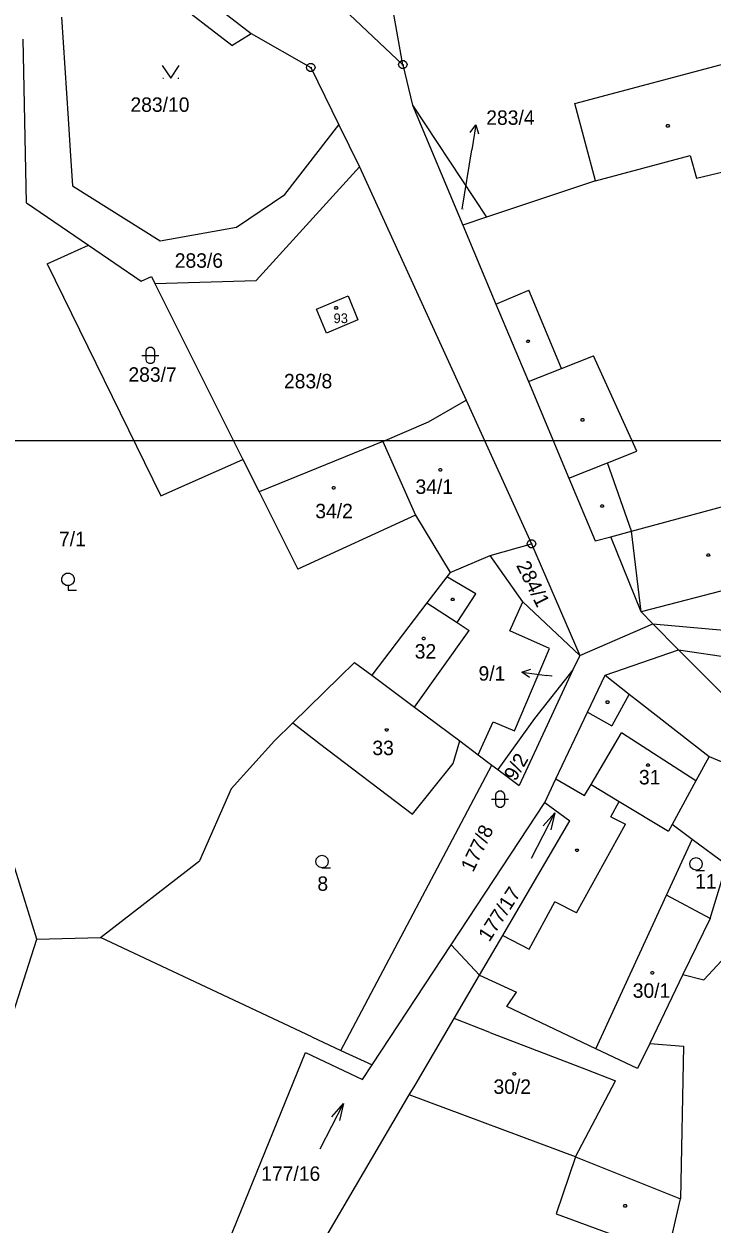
# Model space of a CAD drawing. Extents: x -780000 to -777378, y -1011169 to -1009297.
# Drawn here: x -779250.3 to -779169.3, y -1010360.1 to -1010218.8 of the extents above; entities that cross this region are included whole.
import ezdxf

# ---------------------------------------------------------------- set-up
doc = ezdxf.new("R2010")
doc.units = 0
for name, color, linetype in [('Default', 7, 'Continuous'), ('KN_HRANICE', 7, 'Continuous'), ('KN_KULTURY', 7, 'Continuous'), ('KN_PARCELY', 7, 'Continuous'), ('KN_SLUCKY', 7, 'Continuous'), ('LEGENDA', 7, 'Continuous')]:
    doc.layers.add(name, color=color, linetype=linetype)

# ---------------------------------------------------------------- blocks, each defined once
blk = doc.blocks.new('304')
at = {"layer": 'Default'}
blk.add_lwpolyline([(0, 0), (-0.38, 0.1), (-0.65, 0.37), (-0.75, 0.74), (-0.65, 1.11), (-0.38, 1.38), (-0.01, 1.48), (0.36, 1.38), (0.63, 1.11), (0.73, 0.73), (0.63, 0.35), (0.36, 0.08), (-0.02, -0.02), (0.98, -0.02)], dxfattribs=at)
blk = doc.blocks.new('305')
at = {"layer": 'Default'}
blk.add_lwpolyline([(0, 0.53), (-0.19, 0.53), (-0.53, 0.72), (-0.72, 1.06), (-0.72, 1.45), (-0.53, 1.79), (-0.19, 1.98), (0.2, 1.98), (0.54, 1.79), (0.73, 1.45), (0.73, 1.06), (0.54, 0.72), (0.2, 0.53), (0.01, 0.53), (0.01, 0), (1.01, 0)], dxfattribs=at)
blk = doc.blocks.new('314')
at = {"layer": 'Default'}
for p, q in [((-0.95, 0), (-0.85, 0)), ((0.85, 0), (0.95, 0))]:
    blk.add_line(p, q, dxfattribs=at)
blk.add_lwpolyline([(-1, 1.5), (0, 0), (1, 1.5)], dxfattribs=at)
blk = doc.blocks.new('316')
at = {"layer": 'Default'}
for points in [[(-0.5, 1.5), (-0.4, 1.79), (-0.15, 1.97), (0.16, 1.97), (0.41, 1.79), (0.51, 1.5), (0.51, 0.5), (0.41, 0.21), (0.16, 0.03), (-0.15, 0.03), (-0.4, 0.21), (-0.5, 0.5), (-0.5, 1.5)], [(-1, 1), (0.27, 1), (1, 1)]]:
    blk.add_lwpolyline(points, dxfattribs=at)
blk = doc.blocks.new('NAHRADNI_SYMBOL')
at = {"layer": 'Default'}
blk.add_lwpolyline([(0.09, 0.15), (0.18, 0), (0.09, -0.15), (-0.09, -0.15), (-0.18, 0), (-0.09, 0.15), (0.09, 0.15)], dxfattribs=at)
blk = doc.blocks.new('802')
at = {"layer": 'Default'}
blk.add_line((-3, 0), (3, 0), dxfattribs=at)
blk.add_lwpolyline([(1, 0.5), (3, 0), (1, -0.5)], dxfattribs=at)
blk = doc.blocks.new('10292')
at = {"layer": 'Default'}
blk.add_line((0, 3), (0, 0), dxfattribs=at)
blk.add_lwpolyline([(-0.5, 2), (0, 3), (0.5, 2)], dxfattribs=at)
blk = doc.blocks.new('402')
at = {"layer": 'Default'}
blk.add_lwpolyline([(0.09, 0.15), (0.18, 0), (0.09, -0.15), (-0.09, -0.15), (-0.18, 0), (-0.09, 0.15), (0.09, 0.15)], dxfattribs=at)
blk = doc.blocks.new('105')
at = {"layer": 'Default'}
blk.add_line((-0.12, 0), (0.12, 0), dxfattribs=at)
blk.add_lwpolyline([(0.15, 0.48), (0.4, 0.3), (0.5, 0.01), (0.4, -0.28), (0.15, -0.46), (-0.16, -0.46), (-0.41, -0.28), (-0.51, 0.01), (-0.41, 0.3), (-0.16, 0.48), (0.15, 0.48)], dxfattribs=at)

msp = doc.modelspace()

# ---------------------------------------------------------------- linework, layer by layer
at = {"layer": 'KN_HRANICE'}
for p, q in [((-779205.69, -1010223.63), (-779207.96, -1010210.85)), ((-779234.04, -1010211.86), (-779223.57, -1010219.94)), ((-779225.85, -1010221.36), (-779236.27, -1010213.3)), ((-779213.39, -1010216.37), (-779205.69, -1010223.63)), ((-779245.92, -1010218.02), (-779245.13, -1010229.97)), ((-779225.85, -1010221.36), (-779223.57, -1010219.94)), ((-779223.57, -1010219.94), (-779216.54, -1010223.96)), ((-779250.04, -1010239.9), (-779250.45, -1010220.64)), ((-779216.54, -1010223.96), (-779213.22, -1010230.72)), ((-779205.69, -1010223.63), (-779204.56, -1010228.41)), ((-779185.42, -1010228.21), (-779166.52, -1010223.19)), ((-779204.56, -1010228.41), (-779198.63, -1010242.53)), ((-779204.56, -1010228.41), (-779195.85, -1010241.6)), ((-779182.98, -1010237.3), (-779185.42, -1010228.21)), ((-779245.13, -1010229.97), (-779244.88, -1010233.78)), ((-779219.59, -1010238.93), (-779213.22, -1010230.72)), ((-779213.22, -1010230.72), (-779210.79, -1010235.65)), ((-779244.88, -1010233.78), (-779244.61, -1010237.88)), ((-779222.98, -1010249.03), (-779210.79, -1010235.65)), ((-779210.79, -1010235.65), (-779198.24, -1010263.13)), ((-779244.61, -1010237.88), (-779234.3, -1010244.39)), ((-779182.98, -1010237.3), (-779195.85, -1010241.6)), ((-779225.31, -1010242.76), (-779219.59, -1010238.93)), ((-779250.04, -1010239.9), (-779242.75, -1010244.88)), ((-779248.83, -1010326.61), (-779275.45, -1010241.64)), ((-779195.85, -1010241.6), (-779198.63, -1010242.53)), ((-779198.63, -1010242.53), (-779194.73, -1010251.82)), ((-779234.3, -1010244.39), (-779225.31, -1010242.76)), ((-779247.62, -1010247.08), (-779242.75, -1010244.88)), ((-779242.75, -1010244.88), (-779236.53, -1010249.13)), ((-779247.62, -1010247.08), (-779234.22, -1010274.39)), ((-779236.53, -1010249.13), (-779235.31, -1010248.59)), ((-779235.31, -1010248.59), (-779234.91, -1010249.39)), ((-779234.91, -1010249.39), (-779222.98, -1010249.03)), ((-779234.91, -1010249.39), (-779224.53, -1010270.12)), ((-779215.86, -1010252.41), (-779212.13, -1010250.84)), ((-779212.13, -1010250.84), (-779211.01, -1010253.67)), ((-779214.7, -1010255.23), (-779215.86, -1010252.41)), ((-779194.73, -1010251.82), (-779190.9, -1010260.95)), ((-779211.01, -1010253.67), (-779214.7, -1010255.23)), ((-779190.9, -1010260.95), (-779186.13, -1010272.3)), ((-779202.67, -1010265.7), (-779198.24, -1010263.13)), ((-779198.24, -1010263.13), (-779190.52, -1010280.05)), ((-779208.06, -1010267.99), (-779202.67, -1010265.7)), ((-779208.06, -1010267.99), (-779222.63, -1010273.91)), ((-779208.06, -1010267.99), (-779204.18, -1010276.69)), ((-779234.22, -1010274.39), (-779224.53, -1010270.12)), ((-779224.53, -1010270.12), (-779222.63, -1010273.91)), ((-779186.13, -1010272.3), (-779183.03, -1010279.71)), ((-779222.63, -1010273.91), (-779218.06, -1010283.04)), ((-779204.18, -1010276.69), (-779218.06, -1010283.04)), ((-779204.18, -1010276.69), (-779202.14, -1010280.06)), ((-779183.03, -1010279.71), (-779181.19, -1010279.22)), ((-779177.62, -1010288.07), (-779181.19, -1010279.22)), ((-779202.14, -1010280.06), (-779200.12, -1010283.41)), ((-779195.39, -1010281.41), (-779190.52, -1010280.05)), ((-779190.52, -1010280.05), (-779184.85, -1010293.19)), ((-779200.12, -1010283.41), (-779195.39, -1010281.41)), ((-779191.55, -1010286.87), (-779195.39, -1010281.41)), ((-779200.12, -1010283.41), (-779200.51, -1010283.92)), ((-779159.28, -1010283.29), (-779177.62, -1010288.07)), ((-779200.51, -1010283.92), (-779202.85, -1010286.98)), ((-779202.85, -1010286.98), (-779209.36, -1010295.51)), ((-779193.1, -1010290.28), (-779191.55, -1010286.87)), ((-779191.55, -1010286.87), (-779184.85, -1010293.19)), ((-779177.62, -1010288.07), (-779176.23, -1010289.47)), ((-779188.41, -1010292.39), (-779193.1, -1010290.28)), ((-779184.85, -1010293.19), (-779176.23, -1010289.47)), ((-779176.23, -1010289.47), (-779173.19, -1010292.52)), ((-779176.23, -1010289.47), (-779156.62, -1010291.23)), ((-779192.55, -1010302.07), (-779188.41, -1010292.39)), ((-779184.85, -1010293.19), (-779185.64, -1010294.9)), ((-779181.85, -1010295.53), (-779173.19, -1010292.52)), ((-779173.19, -1010292.52), (-779168.03, -1010297.71)), ((-779173.19, -1010292.52), (-779166.79, -1010293.46)), ((-779211.37, -1010294.01), (-779213.17, -1010295.76)), ((-779211.37, -1010294.01), (-779209.36, -1010295.51)), ((-779213.17, -1010295.76), (-779218.66, -1010301.14)), ((-779209.36, -1010295.51), (-779204.33, -1010299.27)), ((-779185.64, -1010294.9), (-779191.98, -1010308.5)), ((-779183.92, -1010299.88), (-779181.85, -1010295.53)), ((-779181.85, -1010295.53), (-779179.01, -1010297.75)), ((-779179.01, -1010297.75), (-779177.81, -1010298.69)), ((-779177.81, -1010298.69), (-779169.61, -1010305.1)), ((-779204.33, -1010299.27), (-779198.99, -1010303.26)), ((-779187.65, -1010307.74), (-779183.92, -1010299.88)), ((-779218.66, -1010301.14), (-779220.82, -1010303.25)), ((-779218.66, -1010301.14), (-779215.5, -1010303.55)), ((-779196.83, -1010304.88), (-779195.06, -1010301.02)), ((-779195.06, -1010301.02), (-779192.55, -1010302.07)), ((-779225.92, -1010308.91), (-779220.82, -1010303.25)), ((-779199.75, -1010305.93), (-779198.99, -1010303.26)), ((-779198.99, -1010303.26), (-779196.83, -1010304.88)), ((-779215.5, -1010303.55), (-779204.57, -1010311.9)), ((-779212.98, -1010339.7), (-779195.2, -1010306.1)), ((-779204.57, -1010311.9), (-779199.75, -1010305.93)), ((-779196.83, -1010304.88), (-779195.2, -1010306.1)), ((-779195.2, -1010306.1), (-779194.49, -1010306.63)), ((-779169.61, -1010305.1), (-779171.15, -1010307.94)), ((-779169.61, -1010305.1), (-779160.99, -1010308.63)), ((-779194.49, -1010306.63), (-779191.98, -1010308.5)), ((-779225.92, -1010308.91), (-779229.64, -1010317.38)), ((-779188.97, -1010310.51), (-779187.65, -1010307.74)), ((-779187.65, -1010307.74), (-779184.27, -1010309.7)), ((-779184.27, -1010309.7), (-779183.51, -1010308.4)), ((-779183.51, -1010308.4), (-779180.21, -1010310.38)), ((-779171.15, -1010307.94), (-779173.96, -1010313.1)), ((-779180.21, -1010310.38), (-779174.39, -1010313.89)), ((-779200, -1010327.27), (-779188.97, -1010310.51)), ((-779188.97, -1010310.51), (-779186, -1010312.66)), ((-779190.73, -1010320.73), (-779186, -1010312.66)), ((-779173.96, -1010313.1), (-779174.39, -1010313.89)), ((-779171.61, -1010314.85), (-779173.96, -1010313.1)), ((-779174.62, -1010321.41), (-779171.61, -1010314.85)), ((-779167.55, -1010317.87), (-779171.61, -1010314.85)), ((-779241.34, -1010326.4), (-779229.64, -1010317.38)), ((-779169.49, -1010324.18), (-779167.55, -1010317.87)), ((-779193.92, -1010326.17), (-779190.73, -1010320.73)), ((-779169.49, -1010324.18), (-779174.62, -1010321.41)), ((-779169.49, -1010324.18), (-779172.68, -1010330.78)), ((-779253.82, -1010342.15), (-779248.83, -1010326.61)), ((-779248.83, -1010326.61), (-779241.34, -1010326.4)), ((-779216.41, -1010338.1), (-779241.34, -1010326.4)), ((-779209.31, -1010341.42), (-779200, -1010327.27)), ((-779200, -1010327.27), (-779196.66, -1010330.84)), ((-779196.66, -1010330.84), (-779193.92, -1010326.17)), ((-779170.22, -1010331.41), (-779167.12, -1010328.04)), ((-779199.66, -1010335.95), (-779196.66, -1010330.84)), ((-779196.66, -1010330.84), (-779192.3, -1010332.84)), ((-779172.68, -1010330.78), (-779176.6, -1010338.9)), ((-779172.68, -1010330.78), (-779170.22, -1010331.41)), ((-779193.43, -1010334.55), (-779192.3, -1010332.84)), ((-779182.94, -1010339.51), (-779193.43, -1010334.55)), ((-779204.25, -1010343.79), (-779199.66, -1010335.95)), ((-779216.41, -1010338.1), (-779212.98, -1010339.7)), ((-779227.1, -1010364.33), (-779217.17, -1010339.95)), ((-779212.98, -1010339.7), (-779209.31, -1010341.42)), ((-779178.02, -1010341.84), (-779182.94, -1010339.51)), ((-779176.6, -1010338.9), (-779178.02, -1010341.84)), ((-779176.6, -1010338.9), (-779172.6, -1010339.21)), ((-779172.6, -1010339.21), (-779172.96, -1010357.18)), ((-779204.93, -1010344.94), (-779204.25, -1010343.79)), ((-779217.76, -1010366.81), (-779204.93, -1010344.94)), ((-779185.33, -1010352.25), (-779204.93, -1010344.94)), ((-779185.33, -1010352.25), (-779187.61, -1010358.93)), ((-779174.51, -1010363.75), (-779172.96, -1010357.18)), ((-779187.61, -1010358.93), (-779174.51, -1010363.75))]:
    msp.add_line(p, q, dxfattribs=at)
for points in [[(-779185.64, -1010294.9), (-779190.18, -1010300.61), (-779194.49, -1010306.63)], [(-779217.17, -1010339.95), (-779210.43, -1010343.11), (-779209.31, -1010341.42)]]:
    msp.add_lwpolyline(points, dxfattribs=at)
at = {"layer": 'KN_PARCELY'}
for p, q in [((-779198.7, -1010240.65), (-779197.58, -1010233.67)), ((-779188.12, -1010295.64), (-779188.71, -1010295.56))]:
    msp.add_line(p, q, dxfattribs=at)
at = {"layer": 'KN_SLUCKY'}
for p, q in [((-779182.98, -1010237.3), (-779171.83, -1010234.32)), ((-779171.83, -1010234.32), (-779171.09, -1010237.01)), ((-779171.09, -1010237.01), (-779166.12, -1010235.81)), ((-779194.73, -1010251.82), (-779190.86, -1010250.19)), ((-779186.99, -1010259.4), (-779190.86, -1010250.19)), ((-779186.99, -1010259.4), (-779183.21, -1010257.9)), ((-779178.12, -1010269.14), (-779183.21, -1010257.9)), ((-779190.9, -1010260.95), (-779186.99, -1010259.4)), ((-779181.59, -1010270.51), (-779178.12, -1010269.14)), ((-779186.13, -1010272.3), (-779181.59, -1010270.51)), ((-779178.75, -1010278.56), (-779181.59, -1010270.51)), ((-779178.75, -1010278.56), (-779161.78, -1010273.99)), ((-779181.19, -1010279.22), (-779178.75, -1010278.56)), ((-779177.62, -1010288.07), (-779178.75, -1010278.56)), ((-779197.09, -1010285.92), (-779200.51, -1010283.92)), ((-779199.3, -1010289.31), (-779197.09, -1010285.92)), ((-779202.85, -1010286.98), (-779199.3, -1010289.31)), ((-779204.33, -1010299.27), (-779197.88, -1010290.24)), ((-779199.3, -1010289.31), (-779197.88, -1010290.24)), ((-779179.01, -1010297.75), (-779181.08, -1010301.49)), ((-779183.92, -1010299.88), (-779181.08, -1010301.49)), ((-779183.51, -1010308.4), (-779179.93, -1010302.29)), ((-779171.15, -1010307.94), (-779179.93, -1010302.29)), ((-779181.18, -1010312.2), (-779180.21, -1010310.38)), ((-779185.22, -1010323.51), (-779179.44, -1010313.05)), ((-779181.18, -1010312.2), (-779179.44, -1010313.05)), ((-779182.94, -1010339.51), (-779174.62, -1010321.41)), ((-779190.79, -1010327.79), (-779187.78, -1010322.22)), ((-779185.22, -1010323.51), (-779187.78, -1010322.22)), ((-779193.92, -1010326.17), (-779190.79, -1010327.79)), ((-779195.44, -1010337.58), (-779199.66, -1010335.95)), ((-779195.44, -1010337.58), (-779184.06, -1010341.97)), ((-779184.06, -1010341.97), (-779180.63, -1010343.29)), ((-779185.33, -1010352.25), (-779180.63, -1010343.29)), ((-779185.33, -1010352.25), (-779172.96, -1010357.18))]:
    msp.add_line(p, q, dxfattribs=at)
at = {"layer": 'LEGENDA'}
msp.add_lwpolyline([(-779530.66, -1010687.91), (-778936.66, -1010687.91), (-778936.66, -1010267.91), (-779530.66, -1010267.91)], close=True, dxfattribs=at)

# ---------------------------------------------------------------- block references
at = {"layer": 'KN_KULTURY'}
for name, p in [('314', (-779233.04, -1010225.22)), ('402', (-779174.46, -1010230.82)), ('402', (-779213.55, -1010252.26)), ('402', (-779190.93, -1010256.2)), ('316', (-779235.45, -1010258.86)), ('402', (-779184.52, -1010265.45)), ('NAHRADNI_SYMBOL', (-779201.27, -1010271.33)), ('402', (-779213.85, -1010273.46)), ('402', (-779182.2, -1010275.59)), ('402', (-779169.68, -1010281.37)), ('305', (-779245.16, -1010285.49)), ('402', (-779199.83, -1010286.59)), ('402', (-779203.23, -1010291.21)), ('402', (-779181.57, -1010298.69)), ('NAHRADNI_SYMBOL', (-779207.6, -1010301.97)), ('402', (-779176.81, -1010306.1)), ('316', (-779194.24, -1010311.11)), ('402', (-779185.16, -1010316.14)), ('304', (-779215.21, -1010318.2)), ('304', (-779171.13, -1010318.48)), ('402', (-779176.29, -1010330.58)), ('402', (-779192.55, -1010342.47)), ('402', (-779179.49, -1010358))]:
    msp.add_blockref(name, p, dxfattribs=at)
at = {"layer": 'KN_KULTURY', "rotation": 62.796174}
for p in [(-779189.15, -1010314.39), (-779214.06, -1010348.63)]:
    msp.add_blockref('802', p, dxfattribs=at)
at = {"layer": 'KN_PARCELY'}
for p in [(-779216.54, -1010223.96), (-779205.69, -1010223.63), (-779190.52, -1010280.05)]:
    msp.add_blockref('105', p, dxfattribs=at)
for p, rotation in [((-779197.58, -1010233.67), -9.120646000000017), ((-779188.71, -1010295.56), 82.162148)]:
    msp.add_blockref('10292', p, dxfattribs=dict(at, rotation=rotation))

# ---------------------------------------------------------------- texts
for s, height, p in [('283/10', 1.7, (-779237.79, -1010229.18)), ('283/4', 1.7, (-779195.86, -1010230.71)), ('283/4', 0.1, (-779198.69, -1010240.65)), ('283/6', 1.7, (-779232.57, -1010247.54)), ('93', 1.14, (-779213.86, -1010254.06)), ('283/7', 1.7, (-779238.03, -1010260.96)), ('283/8', 1.7, (-779219.7, -1010261.74)), ('34/1', 1.7, (-779204.2, -1010274.17)), ('34/2', 1.7, (-779216.01, -1010277.04)), ('7/1', 1.7, (-779246.21, -1010280.33)), ('32', 1.7, (-779204.29, -1010293.56)), ('9/1', 1.7, (-779196.77, -1010296.16)), ('9/1', 0.1, (-779188.25, -1010295.64)), ('33', 1.7, (-779209.28, -1010304.93)), ('31', 1.7, (-779177.87, -1010308.38)), ('8', 1.7, (-779215.76, -1010320.91)), ('11', 1.7, (-779171.25, -1010320.64)), ('30/1', 1.7, (-779178.6, -1010333.51)), ('30/2', 1.7, (-779195.01, -1010344.82)), ('177/16', 1.7, (-779222.38, -1010355.06))]:
    msp.add_text(s, height=height, dxfattribs=at).set_placement(p)
for s, rotation, p in [('284/1', 296.563, (-779192.37, -1010282.58)), ('9/2', 59.874, (-779192.42, -1010308.1)), ('177/8', 64.4, (-779197.41, -1010318.81)), ('177/17', 56.952, (-779195.5, -1010327.01))]:
    msp.add_text(s, height=1.7, rotation=rotation, dxfattribs=at).set_placement(p)

doc.saveas('drawing.dxf')
